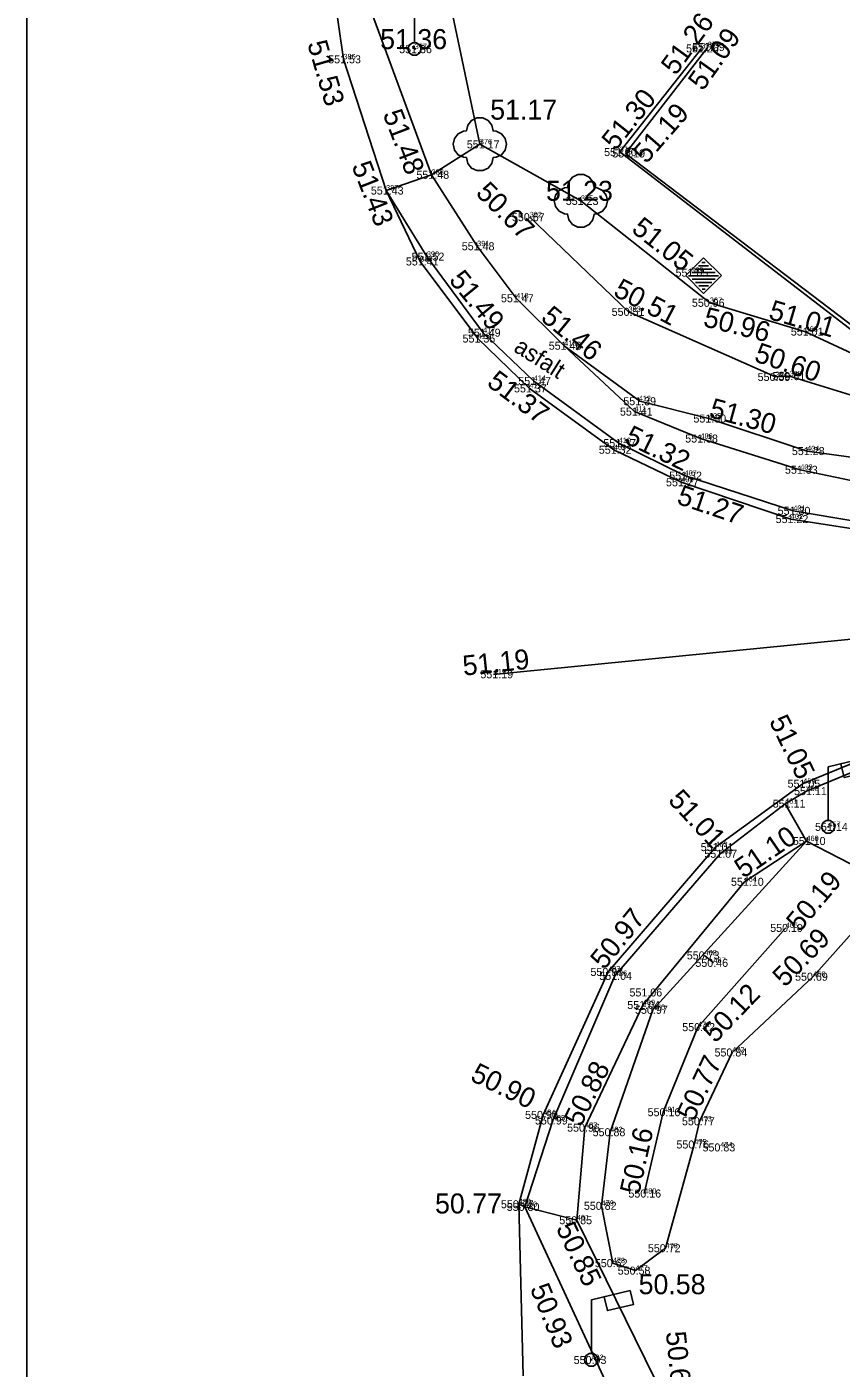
# Model space of a CAD drawing. Extents: x -866693 to -866303, y -1041966 to -1040244.
# Drawn here: x -866692.5 to -866662, y -1040325.4 to -1040275.1 of the extents above; entities that cross this region are included whole.
import ezdxf

# ---------------------------------------------------------------- set-up
doc = ezdxf.new("R2010")
doc.units = 0
for name, color, linetype in [('1 hrana zpevněné komunikace-plocha', 7, 'Continuous'), ('2 hrana nezpevněné komunikace-plocha', 7, 'Continuous'), ('3 osa komunikace', 7, 'Continuous'), ('43 lampa', 7, 'Continuous'), ('5 obrubník nahoře (chodník)', 7, 'Continuous'), ('56 přítokové nebo odtokové potrubí', 7, 'Continuous'), ('60 strom bez rozlišení', 7, 'Continuous'), ('7 hrana svah nahoře', 7, 'Continuous'), ('8 hrana svah dole', 7, 'Continuous'), ('80 šachta hranatá', 7, 'Continuous'), ('Bod', 7, 'Continuous'), ('Formát', 7, 'Continuous'), ('Nadmořská výška', 7, 'Continuous'), ('Nadmořská výška_tisk', 7, 'Continuous'), ('popisy', 7, 'Continuous'), ('Číslo bodu', 7, 'Continuous')]:
    doc.layers.add(name, color=color, linetype=linetype)

msp = doc.modelspace()

# ---------------------------------------------------------------- linework, layer by layer
at = {"layer": '1 hrana zpevněné komunikace-plocha'}
msp.add_line((-866682.858, -1040260.807), (-866680.652, -1040276.337), dxfattribs=at)
for points in [[(-866680.652, -1040276.337), (-866679.05, -1040281.256), (-866677.765, -1040283.923), (-866675.61, -1040286.809), (-866673.678, -1040288.676), (-866670.504, -1040290.984), (-866667.979, -1040292.197), (-866663.869, -1040293.577), (-866661.368, -1040293.969), (-866659.169, -1040293.985), (-866654.661, -1040293.593), (-866639.503, -1040291.517), (-866622.442, -1040289.146), (-866600.706, -1040285.969), (-866598.4, -1040283.431), (-866597.694, -1040282.088), (-866597.528, -1040280.555), (-866597.782, -1040279.514), (-866598.357, -1040278.559), (-866599.338, -1040277.433), (-866600.156, -1040276.793), (-866601.514, -1040276.109), (-866603.056, -1040275.634), (-866606.248, -1040276.054)], [(-866666.987, -1040275.884), (-866670.068, -1040279.868), (-866659.728, -1040287.726), (-866655.805, -1040287.173), (-866643.973, -1040285.546)], [(-866503.553, -1040279.722), (-866523.034, -1040282.41), (-866541.374, -1040284.946), (-866561.808, -1040287.782), (-866574.398, -1040289.556), (-866602.398, -1040293.439), (-866619.972, -1040295.863), (-866638.769, -1040298.486), (-866650.196, -1040300.008), (-866657.766, -1040301.183), (-866663.405, -1040303.497), (-866666.7, -1040305.877), (-866670.718, -1040310.555), (-866673.161, -1040315.92), (-866674.075, -1040319.269), (-866673.907, -1040325.701)], [(-866679.05, -1040281.256), (-866677.344, -1040280.668), (-866675.636, -1040283.345), (-866674.167, -1040285.302), (-866672.37, -1040287.081), (-866669.737, -1040289.547), (-866667.26, -1040290.563), (-866663.515, -1040291.727), (-866660.9, -1040292.279)], [(-866673.847, -1040319.369), (-866671.893, -1040319.868), (-866671.591, -1040316.396), (-866669.422, -1040311.802), (-866665.606, -1040307.176), (-866663.286, -1040305.651)]]:
    msp.add_lwpolyline(points, dxfattribs=at)
at = {"layer": '2 hrana nezpevněné komunikace-plocha'}
for p, q in [((-866673.847, -1040319.369), (-866670.276, -1040327.071)), ((-866671.893, -1040319.868), (-866668.444, -1040326.89))]:
    msp.add_line(p, q, dxfattribs=at)
at = {"layer": '3 osa komunikace'}
msp.add_lwpolyline([(-866675.016, -1040299.403), (-866658.944, -1040297.823), (-866639.253, -1040295.089), (-866620.168, -1040292.742), (-866603.167, -1040290.212), (-866574.251, -1040285.999), (-866539.891, -1040281.121), (-866503.725, -1040276.174)], dxfattribs=at)
at = {"layer": '43 lampa'}
for points in [[(-866677.978, -1040275.717), (-866677.903, -1040275.717), (-866677.778, -1040275.807), (-866677.728, -1040275.952), (-866677.778, -1040276.097), (-866677.903, -1040276.187), (-866678.058, -1040276.187), (-866678.183, -1040276.097), (-866678.233, -1040275.952), (-866678.183, -1040275.807), (-866678.058, -1040275.717), (-866677.978, -1040275.717), (-866677.978, -1040273.707), (-866676.528, -1040273.357), (-866676.403, -1040273.882), (-866677.378, -1040274.107), (-866677.503, -1040273.592)], [(-866678.008, -1040275.957), (-866677.948, -1040275.957)], [(-866662.465, -1040304.882), (-866662.39, -1040304.882), (-866662.265, -1040304.972), (-866662.215, -1040305.117), (-866662.265, -1040305.262), (-866662.39, -1040305.352), (-866662.545, -1040305.352), (-866662.67, -1040305.262), (-866662.72, -1040305.117), (-866662.67, -1040304.972), (-866662.545, -1040304.882), (-866662.465, -1040304.882), (-866662.465, -1040302.872), (-866661.015, -1040302.522), (-866660.89, -1040303.047), (-866661.865, -1040303.272), (-866661.99, -1040302.757)], [(-866662.495, -1040305.122), (-866662.435, -1040305.122)], [(-866671.35, -1040324.867), (-866671.275, -1040324.867), (-866671.15, -1040324.957), (-866671.1, -1040325.102), (-866671.15, -1040325.247), (-866671.275, -1040325.337), (-866671.43, -1040325.337), (-866671.555, -1040325.247), (-866671.605, -1040325.102), (-866671.555, -1040324.957), (-866671.43, -1040324.867), (-866671.35, -1040324.867), (-866671.35, -1040322.857), (-866669.9, -1040322.507), (-866669.775, -1040323.032), (-866670.75, -1040323.257), (-866670.875, -1040322.742)], [(-866671.38, -1040325.107), (-866671.32, -1040325.107)]]:
    msp.add_lwpolyline(points, dxfattribs=at)
at = {"layer": '5 obrubník nahoře (chodník)'}
msp.add_line((-866663.286, -1040305.651), (-866664.088, -1040304.254), dxfattribs=at)
for points in [[(-866605.449, -1040280.624), (-866622.897, -1040282.952), (-866640.93, -1040285.241), (-866655.388, -1040287.291), (-866659.769, -1040287.9), (-866670.289, -1040279.815), (-866667.222, -1040275.931)], [(-866622.418, -1040288.878), (-866639.572, -1040291.228), (-866654.686, -1040293.361), (-866659.163, -1040293.711), (-866661.316, -1040293.679), (-866663.777, -1040293.268), (-866667.855, -1040291.946), (-866670.326, -1040290.728), (-866673.518, -1040288.396), (-866675.414, -1040286.594), (-866677.519, -1040283.739), (-866679.05, -1040281.256)], [(-866574.644, -1040289.831), (-866602.365, -1040293.689), (-866619.938, -1040296.168), (-866638.627, -1040298.746), (-866650.109, -1040300.299), (-866657.681, -1040301.458), (-866663.286, -1040303.778), (-866664.088, -1040304.254), (-866666.526, -1040306.133), (-866670.469, -1040310.707), (-866672.797, -1040316.126), (-866673.847, -1040319.369), (-866674.075, -1040319.269)]]:
    msp.add_lwpolyline(points, dxfattribs=at)
at = {"layer": '56 přítokové nebo odtokové potrubí'}
msp.add_line((-866666.775, -1040310.22), (-866667.107, -1040309.938), dxfattribs=at)
at = {"layer": '60 strom bez rozlišení'}
for points in [[(-866674.534, -1040279.525), (-866674.584, -1040279.742), (-866674.723, -1040279.916), (-866674.923, -1040280.013), (-866675.034, -1040280.025), (-866675.084, -1040280.242), (-866675.223, -1040280.416), (-866675.423, -1040280.513), (-866675.645, -1040280.513), (-866675.846, -1040280.416), (-866675.985, -1040280.242), (-866676.034, -1040280.025), (-866676.145, -1040280.013), (-866676.346, -1040279.916), (-866676.485, -1040279.742), (-866676.534, -1040279.525), (-866676.485, -1040279.308), (-866676.346, -1040279.134), (-866676.145, -1040279.037), (-866676.034, -1040279.025), (-866675.985, -1040278.808), (-866675.846, -1040278.634), (-866675.645, -1040278.537), (-866675.423, -1040278.537), (-866675.223, -1040278.634), (-866675.084, -1040278.808), (-866675.034, -1040279.025), (-866674.923, -1040279.037), (-866674.723, -1040279.134), (-866674.584, -1040279.308)], [(-866670.744, -1040281.646), (-866670.794, -1040281.863), (-866670.932, -1040282.037), (-866671.133, -1040282.133), (-866671.244, -1040282.146), (-866671.294, -1040282.363), (-866671.432, -1040282.537), (-866671.633, -1040282.633), (-866671.855, -1040282.633), (-866672.056, -1040282.537), (-866672.194, -1040282.363), (-866672.244, -1040282.146), (-866672.355, -1040282.133), (-866672.556, -1040282.037), (-866672.694, -1040281.863), (-866672.744, -1040281.646), (-866672.694, -1040281.429), (-866672.556, -1040281.255), (-866672.355, -1040281.159), (-866672.244, -1040281.146), (-866672.194, -1040280.929), (-866672.056, -1040280.755), (-866671.855, -1040280.659), (-866671.633, -1040280.659), (-866671.432, -1040280.755), (-866671.294, -1040280.929), (-866671.244, -1040281.146), (-866671.133, -1040281.159), (-866670.932, -1040281.255), (-866670.794, -1040281.429)]]:
    msp.add_lwpolyline(points, close=True, dxfattribs=at)
for points in [[(-866675.559, -1040279.525), (-866675.534, -1040279.525), (-866675.509, -1040279.525)], [(-866671.769, -1040281.646), (-866671.744, -1040281.646), (-866671.719, -1040281.646)]]:
    msp.add_lwpolyline(points, dxfattribs=at)
at = {"layer": '7 hrana svah nahoře'}
for p, q in [((-866679.722, -1040259.575), (-866675.534, -1040279.525)), ((-866680.028, -1040273.381), (-866677.344, -1040280.668))]:
    msp.add_line(p, q, dxfattribs=at)
for points in [[(-866641.023, -1040285.345), (-866655.356, -1040287.857), (-866659.328, -1040288.407), (-866663.323, -1040286.553), (-866666.909, -1040285.472), (-866671.744, -1040281.646), (-866675.534, -1040279.525), (-866677.344, -1040280.668)], [(-866658.299, -1040291.361), (-866659.336, -1040291.575), (-866663.261, -1040291.033), (-866666.944, -1040289.807), (-866669.527, -1040289.157), (-866672.37, -1040287.081)]]:
    msp.add_lwpolyline(points, dxfattribs=at)
msp.add_lwpolyline([(-866663.286, -1040305.651), (-866660.007, -1040307.34), (-866663.035, -1040310.735), (-866666.071, -1040313.575), (-866667.292, -1040316.164), (-866667.49, -1040317.028), (-866668.573, -1040320.921), (-866669.698, -1040321.759), (-866670.551, -1040321.479), (-866670.968, -1040319.326), (-866670.642, -1040316.567), (-866669.046, -1040311.982)], close=True, dxfattribs=at)
at = {"layer": '8 hrana svah dole'}
for points in [[(-866673.663, -1040282.26), (-866669.958, -1040285.809), (-866664.447, -1040288.251), (-866663.916, -1040288.222), (-866658.723, -1040289.827), (-866656.827, -1040290.616), (-866655.343, -1040289.874), (-866639.933, -1040286.863), (-866622.668, -1040285.165), (-866603.387, -1040282.18), (-866600.979, -1040282.198)], [(-866664.061, -1040308.911), (-866667.357, -1040312.63), (-866668.653, -1040315.815), (-866669.373, -1040318.872)]]:
    msp.add_lwpolyline(points, dxfattribs=at)
at = {"layer": '80 šachta hranatá'}
for p, q in [((-866667.811, -1040284.449), (-866667.143, -1040283.781)), ((-866667.456, -1040284.205), (-866666.829, -1040284.205)), ((-866667.331, -1040284.08), (-866666.954, -1040284.08)), ((-866667.206, -1040283.956), (-866667.081, -1040283.956)), ((-866667.143, -1040283.781), (-866666.472, -1040284.449)), ((-866667.139, -1040285.119), (-866667.811, -1040284.449)), ((-866667.705, -1040284.455), (-866666.578, -1040284.455)), ((-866667.581, -1040284.33), (-866666.703, -1040284.33)), ((-866667.568, -1040284.58), (-866666.713, -1040284.58)), ((-866667.443, -1040284.705), (-866666.838, -1040284.705)), ((-866666.472, -1040284.449), (-866667.139, -1040285.119)), ((-866667.318, -1040284.83), (-866666.962, -1040284.83)), ((-866667.193, -1040284.954), (-866667.086, -1040284.954))]:
    msp.add_line(p, q, dxfattribs=at)
at = {"layer": 'Bod'}
for p, q in [((-866677.978, -1040275.957), (-866677.978, -1040275.957)), ((-866667.222, -1040275.931), (-866667.222, -1040275.931)), ((-866666.987, -1040275.884), (-866666.987, -1040275.884)), ((-866680.652, -1040276.337), (-866680.652, -1040276.337)), ((-866675.534, -1040279.525), (-866675.534, -1040279.525)), ((-866670.289, -1040279.815), (-866670.289, -1040279.815)), ((-866670.068, -1040279.868), (-866670.068, -1040279.868)), ((-866677.344, -1040280.668), (-866677.344, -1040280.668)), ((-866679.05, -1040281.256), (-866679.05, -1040281.256)), ((-866671.744, -1040281.646), (-866671.744, -1040281.646)), ((-866673.663, -1040282.26), (-866673.663, -1040282.26)), ((-866677.519, -1040283.739), (-866677.519, -1040283.739)), ((-866675.636, -1040283.345), (-866675.636, -1040283.345)), ((-866677.765, -1040283.923), (-866677.765, -1040283.923)), ((-866667.142, -1040284.455), (-866667.142, -1040284.455)), ((-866674.167, -1040285.302), (-866674.167, -1040285.302)), ((-866666.909, -1040285.472), (-866666.909, -1040285.472)), ((-866669.958, -1040285.809), (-866669.958, -1040285.809)), ((-866675.414, -1040286.594), (-866675.414, -1040286.594)), ((-866663.323, -1040286.553), (-866663.323, -1040286.553)), ((-866675.61, -1040286.809), (-866675.61, -1040286.809)), ((-866672.37, -1040287.081), (-866672.37, -1040287.081)), ((-866664.447, -1040288.251), (-866664.447, -1040288.251)), ((-866663.916, -1040288.222), (-866663.916, -1040288.222)), ((-866673.678, -1040288.676), (-866673.678, -1040288.676)), ((-866673.518, -1040288.396), (-866673.518, -1040288.396)), ((-866669.577, -1040289.157), (-866669.577, -1040289.157)), ((-866669.737, -1040289.547), (-866669.737, -1040289.547)), ((-866666.944, -1040289.807), (-866666.944, -1040289.807)), ((-866670.326, -1040290.728), (-866670.326, -1040290.728)), ((-866667.26, -1040290.563), (-866667.26, -1040290.563)), ((-866670.504, -1040290.984), (-866670.504, -1040290.984)), ((-866663.261, -1040291.033), (-866663.261, -1040291.033)), ((-866663.515, -1040291.727), (-866663.515, -1040291.727)), ((-866667.979, -1040292.197), (-866667.979, -1040292.197)), ((-866667.855, -1040291.946), (-866667.855, -1040291.946)), ((-866663.777, -1040293.268), (-866663.777, -1040293.268)), ((-866663.869, -1040293.577), (-866663.869, -1040293.577)), ((-866675.016, -1040299.403), (-866675.016, -1040299.403)), ((-866663.405, -1040303.497), (-866663.405, -1040303.497)), ((-866663.286, -1040303.778), (-866663.286, -1040303.778)), ((-866664.088, -1040304.254), (-866664.088, -1040304.254)), ((-866662.465, -1040305.122), (-866662.465, -1040305.122)), ((-866663.286, -1040305.651), (-866663.286, -1040305.651)), ((-866666.7, -1040305.877), (-866666.7, -1040305.877)), ((-866666.526, -1040306.133), (-866666.526, -1040306.133)), ((-866665.606, -1040307.176), (-866665.606, -1040307.176)), ((-866664.061, -1040308.911), (-866664.061, -1040308.911)), ((-866667.107, -1040309.938), (-866667.107, -1040309.938)), ((-866666.775, -1040310.22), (-866666.775, -1040310.22)), ((-866670.718, -1040310.555), (-866670.718, -1040310.555)), ((-866670.469, -1040310.707), (-866670.469, -1040310.707)), ((-866663.035, -1040310.735), (-866663.035, -1040310.735)), ((-866669.422, -1040311.802), (-866669.422, -1040311.802)), ((-866669.046, -1040311.982), (-866669.046, -1040311.982)), ((-866667.357, -1040312.63), (-866667.357, -1040312.63)), ((-866666.071, -1040313.575), (-866666.071, -1040313.575)), ((-866673.161, -1040315.92), (-866673.161, -1040315.92)), ((-866668.653, -1040315.815), (-866668.653, -1040315.815)), ((-866672.797, -1040316.126), (-866672.797, -1040316.126)), ((-866671.591, -1040316.396), (-866671.591, -1040316.396)), ((-866667.292, -1040316.164), (-866667.292, -1040316.164)), ((-866670.642, -1040316.567), (-866670.642, -1040316.567)), ((-866667.49, -1040317.028), (-866667.49, -1040317.028)), ((-866666.518, -1040317.138), (-866666.518, -1040317.138)), ((-866669.373, -1040318.872), (-866669.373, -1040318.872)), ((-866674.075, -1040319.269), (-866674.075, -1040319.269)), ((-866673.847, -1040319.369), (-866673.847, -1040319.369)), ((-866670.968, -1040319.326), (-866670.968, -1040319.326)), ((-866671.893, -1040319.868), (-866671.893, -1040319.868)), ((-866668.573, -1040320.921), (-866668.573, -1040320.921)), ((-866670.551, -1040321.479), (-866670.551, -1040321.479)), ((-866669.698, -1040321.759), (-866669.698, -1040321.759)), ((-866671.35, -1040325.107), (-866671.35, -1040325.107))]:
    msp.add_line(p, q, dxfattribs=at)
at = {"layer": 'Formát'}
msp.add_lwpolyline([(-866692.523, -1040244.107), (-866482.523, -1040244.107), (-866482.523, -1040541.107), (-866692.523, -1040541.107)], close=True, dxfattribs=at)

# ---------------------------------------------------------------- texts
at = {"layer": 'Nadmořská výška'}
for s, p in [('551.53', (-866681.221, -1040276.49)), ('551.36', (-866678.559, -1040276.11)), ('551.26', (-866667.799, -1040276.08)), ('551.09', (-866667.574, -1040276.03)), ('551.17', (-866676.022, -1040279.68)), ('551.30', (-866670.873, -1040279.97)), ('551.19', (-866670.563, -1040280.02)), ('551.48', (-866677.911, -1040280.82)), ('551.43', (-866679.621, -1040281.41)), ('551.23', (-866672.311, -1040281.8)), ('550.67', (-866674.33, -1040282.41)), ('551.48', (-866676.211, -1040283.5)), ('551.52', (-866678.091, -1040283.89)), ('551.41', (-866678.308, -1040284.07)), ('551.05', (-866668.193, -1040284.49)), ('551.47', (-866674.741, -1040285.45)), ('550.51', (-866670.589, -1040285.96)), ('550.96', (-866667.581, -1040285.62)), ('551.35', (-866676.181, -1040286.96)), ('551.49', (-866675.982, -1040286.74)), ('551.01', (-866663.87, -1040286.7)), ('551.46', (-866672.949, -1040287.23)), ('551.47', (-866674.091, -1040288.55)), ('550.59', (-866665.114, -1040288.4)), ('550.61', (-866664.557, -1040288.37)), ('551.37', (-866674.251, -1040288.83)), ('551.39', (-866670.152, -1040289.31)), ('551.41', (-866670.278, -1040289.7)), ('551.30', (-866667.523, -1040289.96)), ('551.37', (-866670.901, -1040290.88)), ('551.38', (-866667.831, -1040290.71)), ('551.32', (-866671.071, -1040291.13)), ('551.28', (-866663.831, -1040291.18)), ('551.33', (-866664.091, -1040291.88)), ('551.27', (-866668.551, -1040292.35)), ('551.32', (-866668.431, -1040292.1)), ('551.30', (-866664.363, -1040293.42)), ('551.22', (-866664.441, -1040293.73)), ('551.19', (-866675.513, -1040299.55)), ('551.05', (-866663.993, -1040303.65)), ('551.11', (-866663.749, -1040303.93)), ('551.11', (-866664.549, -1040304.4)), ('551.14', (-866662.962, -1040305.27)), ('551.01', (-866667.25, -1040306.03)), ('551.10', (-866663.794, -1040305.8)), ('551.07', (-866667.113, -1040306.28)), ('551.10', (-866666.114, -1040307.33)), ('550.19', (-866664.644, -1040309.06)), ('550.73', (-866667.772, -1040310.09)), ('550.46', (-866667.45, -1040310.37)), ('550.97', (-866671.384, -1040310.71)), ('551.04', (-866671.053, -1040310.86)), ('550.69', (-866663.711, -1040310.89)), ('551.06', (-866669.921, -1040311.48)), ('551.04', (-866670.003, -1040311.95)), ('550.97', (-866669.714, -1040312.13)), ('550.12', (-866667.943, -1040312.78)), ('550.84', (-866666.732, -1040313.73)), ('550.90', (-866673.836, -1040316.07)), ('550.16', (-866669.241, -1040315.97)), ('550.99', (-866673.465, -1040316.28)), ('550.96', (-866672.261, -1040316.55)), ('550.88', (-866671.302, -1040316.72)), ('550.77', (-866667.952, -1040316.31)), ('550.76', (-866668.16, -1040317.18)), ('550.83', (-866667.182, -1040317.29)), ('550.16', (-866669.961, -1040319.02)), ('550.77', (-866674.742, -1040319.42)), ('550.80', (-866674.525, -1040319.52)), ('550.82', (-866671.632, -1040319.48)), ('550.85', (-866672.552, -1040320.02)), ('550.72', (-866669.232, -1040321.07)), ('550.62', (-866671.22, -1040321.63)), ('550.58', (-866670.362, -1040321.91)), ('550.93', (-866672.014, -1040325.26))]:
    msp.add_text(s, height=0.3, dxfattribs=at).set_placement(p)
at = {"layer": 'Nadmořská výška_tisk'}
for s, rotation, p in [('51.26', 54.0436, (-866668.19, -1040276.977)), ('51.53', 286.2221, (-866682.011, -1040275.747)), ('51.09', 54.5867, (-866667.171, -1040277.558)), ('51.30', 51.5789, (-866670.439, -1040279.796)), ('51.48', 290.9783, (-866679.182, -1040278.389)), ('51.19', 48.9313, (-866669.289, -1040280.287)), ('51.43', 291.3997, (-866680.352, -1040280.335)), ('50.67', 314.9868, (-866675.721, -1040281.39)), ('51.05', 321.6364, (-866669.885, -1040282.782)), ('51.49', 309.2211, (-866676.72, -1040284.631)), ('50.51', 332.255, (-866670.568, -1040285.184)), ('51.46', 320.4985, (-866673.286, -1040286.098)), ('50.96', 345.8546, (-866667.189, -1040286.342)), ('51.01', 343.5604, (-866664.743, -1040286.065)), ('50.60', 341.3153, (-866665.282, -1040287.653)), ('51.37', 323.019, (-866675.309, -1040288.547)), ('51.30', 344.8075, (-866666.968, -1040289.752)), ('51.32', 334.1656, (-866670.148, -1040290.708)), ('51.27', 341.2757, (-866668.187, -1040292.993)), ('51.19', 6.0608, (-866676.139, -1040299.454)), ('51.05', 295.8753, (-866664.7, -1040301.151)), ('51.01', 312.8339, (-866668.504, -1040304.149)), ('51.10', 34.38, (-866665.652, -1040307.071)), ('50.19', 49.857, (-866663.539, -1040309.099)), ('50.97', 50.8681, (-866670.872, -1040310.512)), ('50.69', 45.8683, (-866664.092, -1040311.163)), ('50.12', 46.3301, (-866666.701, -1040313.256)), ('50.88', 63.7646, (-866671.744, -1040316.401)), ('50.77', 64.664, (-866667.511, -1040316.198)), ('50.90', 333.8878, (-866675.933, -1040314.612)), ('50.16', 77.4768, (-866669.563, -1040318.941)), ('50.85', 295.5254, (-866672.692, -1040320.161)), ('50.93', 292.3709, (-866673.664, -1040322.426)), ('50.69', 275.7625, (-866668.559, -1040324.066))]:
    msp.add_text(s, height=0.75, rotation=rotation, dxfattribs=at).set_placement(p)
for s, p in [('51.36', (-866679.271, -1040275.957)), ('51.17', (-866675.144, -1040278.602)), ('51.23', (-866673.053, -1040281.646)), ('50.77', (-866677.213, -1040319.617)), ('50.58', (-866669.579, -1040322.645))]:
    msp.add_text(s, height=0.75, dxfattribs=at).set_placement(p)
at = {"layer": 'popisy'}
msp.add_text('asfalt', height=0.632, rotation=327.6756, dxfattribs=at).set_placement((-866674.303, -1040287.265))
at = {"layer": 'Číslo bodu'}
for s, p in [('374', (-866666.987, -1040275.884)), ('386', (-866680.652, -1040276.337)), ('377', (-866677.978, -1040275.957)), ('373', (-866667.222, -1040275.931)), ('376', (-866675.534, -1040279.525)), ('372', (-866670.289, -1040279.815)), ('371', (-866670.068, -1040279.868)), ('388', (-866677.344, -1040280.668)), ('387', (-866679.05, -1040281.256)), ('375', (-866671.744, -1040281.646)), ('392', (-866673.663, -1040282.26)), ('391', (-866675.636, -1040283.345)), ('389', (-866677.765, -1040283.923)), ('390', (-866677.519, -1040283.739)), ('369', (-866667.61, -1040284.34)), ('418', (-866674.167, -1040285.302)), ('393', (-866669.958, -1040285.809)), ('367', (-866666.909, -1040285.472)), ('416', (-866675.61, -1040286.809)), ('417', (-866675.414, -1040286.594)), ('366', (-866663.323, -1040286.553)), ('413', (-866672.37, -1040287.081)), ('414', (-866673.518, -1040288.396)), ('394', (-866664.447, -1040288.251)), ('365', (-866663.916, -1040288.222)), ('415', (-866673.678, -1040288.676)), ('412', (-866669.577, -1040289.157)), ('411', (-866669.737, -1040289.547)), ('405', (-866666.944, -1040289.807)), ('409', (-866670.504, -1040290.984)), ('410', (-866670.326, -1040290.728)), ('406', (-866667.26, -1040290.563)), ('404', (-866663.261, -1040291.033)), ('407', (-866667.855, -1040291.946)), ('403', (-866663.515, -1040291.727)), ('408', (-866667.979, -1040292.197)), ('401', (-866663.777, -1040293.268)), ('402', (-866663.869, -1040293.577)), ('419', (-866675.016, -1040299.403)), ('459', (-866663.405, -1040303.497)), ('458', (-866663.286, -1040303.778)), ('461', (-866664.088, -1040304.254)), ('457', (-866662.465, -1040305.122)), ('462', (-866666.7, -1040305.877)), ('460', (-866663.286, -1040305.651)), ('463', (-866666.526, -1040306.133)), ('464', (-866665.606, -1040307.176)), ('465', (-866664.061, -1040308.911)), ('468', (-866667.107, -1040309.938)), ('487', (-866670.718, -1040310.555)), ('467', (-866666.775, -1040310.22)), ('486', (-866670.469, -1040310.707)), ('466', (-866663.035, -1040310.735)), ('469', (-866669.422, -1040311.802)), ('470', (-866669.046, -1040311.982)), ('471', (-866667.357, -1040312.63)), ('472', (-866666.071, -1040313.575)), ('484', (-866673.161, -1040315.92)), ('485', (-866672.797, -1040316.126)), ('481', (-866668.653, -1040315.815)), ('483', (-866671.591, -1040316.396)), ('482', (-866670.642, -1040316.567)), ('473', (-866667.292, -1040316.164)), ('475', (-866667.49, -1040317.028)), ('474', (-866666.518, -1040317.138)), ('480', (-866669.373, -1040318.872)), ('489', (-866674.075, -1040319.269)), ('490', (-866673.847, -1040319.369)), ('479', (-866670.968, -1040319.326)), ('491', (-866671.893, -1040319.868)), ('476', (-866668.573, -1040320.921)), ('478', (-866670.551, -1040321.479)), ('477', (-866669.698, -1040321.759)), ('492', (-866671.35, -1040325.107))]:
    msp.add_text(s, height=0.2, dxfattribs=at).set_placement(p)

doc.saveas('drawing.dxf')
